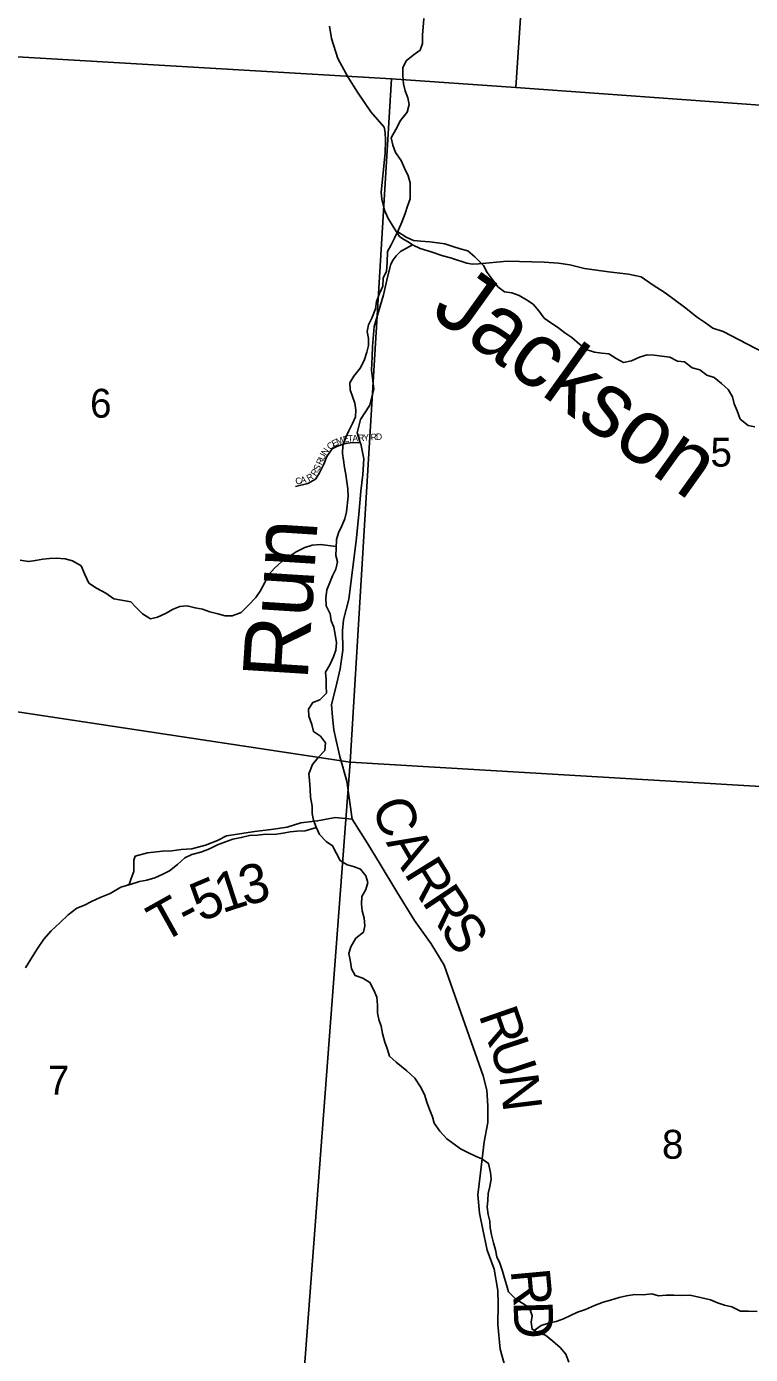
# Model space of a CAD drawing. Extents: x 0 to 34, y 0 to 22.
# Drawn here: x 28.342 to 29.394, y 15.21 to 17.138 of the extents above; entities that cross this region are included whole.
import ezdxf

# ---------------------------------------------------------------- set-up
doc = ezdxf.new("R2010")
doc.units = 0
for name, color, linetype in [('GM_X_County_Road', 7, 'Continuous'), ('GM_X_County_Road_Text', 7, 'Continuous'), ('GM_X_Minor_River', 7, 'Continuous'), ('GM_X_Minor_River_Text', 7, 'Continuous'), ('GM_X_Section', 7, 'Continuous'), ('GM_X_Section_Text', 7, 'Continuous'), ('GM_X_State_Route', 7, 'Continuous'), ('GM_X_Township_Road', 7, 'Continuous'), ('GM_X_Township_Road_Text', 7, 'Continuous'), ('GM_X_Township_Subdivision', 7, 'Continuous'), ('GM_X_Township_Subdivision_Text', 7, 'Continuous')]:
    doc.layers.add(name, color=color, linetype=linetype)

msp = doc.modelspace()

# ---------------------------------------------------------------- linework, layer by layer
at = {"layer": 'GM_X_County_Road'}
msp.add_lwpolyline([(29.036, 15.1969), (29.03, 15.2174), (29.0267, 15.2535), (29.0272, 15.2831), (29.0265, 15.3025), (29.0212, 15.3336), (29.0111, 15.3613), (29.0047, 15.3914), (29.0002, 15.4149), (28.9976, 15.4415), (29.0015, 15.4734), (29.0066, 15.5185), (29.012, 15.5466), (29.0121, 15.5709), (29.0106, 15.5933), (29.0053, 15.6142), (28.9643, 15.7309), (28.9485, 15.775), (28.9296, 15.8058), (28.9054, 15.8396), (28.8798, 15.8815), (28.8556, 15.9214), (28.8367, 15.9526), (28.8148, 15.9869), (28.8074, 16.0419), (28.7972, 16.0777), (28.7916, 16.1012), (28.7882, 16.1168), (28.7864, 16.135), (28.7849, 16.1536), (28.7911, 16.1783), (28.7976, 16.2052), (28.8015, 16.2325), (28.8012, 16.261), (28.8023, 16.2762), (28.8104, 16.3065), (28.8209, 16.3911), (28.8248, 16.4291), (28.8275, 16.4629), (28.8307, 16.4871), (28.8322, 16.5099), (28.8274, 16.5316), (28.8267, 16.5336), (28.8221, 16.5479), (28.8271, 16.5672), (28.8408, 16.5881), (28.8466, 16.6116), (28.8432, 16.6389), (28.844, 16.6583), (28.8445, 16.6731), (28.8472, 16.7023), (28.8606, 16.7482), (28.8669, 16.7756), (28.8713, 16.7926), (28.8745, 16.7988), (28.879, 16.8049), (28.8853, 16.8108), (28.9029, 16.8206)], dxfattribs=at)
at = {"layer": 'GM_X_Minor_River'}
for points in [[(28.919, 17.1492), (28.9183, 17.1367), (28.9173, 17.1257), (28.917, 17.1132), (28.9138, 17.1031), (28.9034, 17.0961), (28.8933, 17.0876), (28.8886, 17.0775), (28.8887, 17.0661), (28.8896, 17.0543), (28.892, 17.0444), (28.8959, 17.0341), (28.898, 17.0245), (28.8947, 17.0132), (28.885, 17.0013), (28.8786, 16.9882), (28.8719, 16.9758), (28.8743, 16.9655), (28.8779, 16.9548), (28.8863, 16.9432), (28.891, 16.9318), (28.8964, 16.921), (28.8992, 16.9107), (28.8994, 16.9001), (28.8991, 16.8876), (28.8954, 16.8767), (28.8922, 16.8661), (28.8873, 16.8537), (28.8825, 16.8424), (28.8766, 16.8304), (28.8715, 16.8207), (28.8663, 16.8109), (28.866, 16.7949)], [(28.8812, 16.8396), (28.8933, 16.8316), (28.9042, 16.8272), (28.9147, 16.8258), (28.928, 16.8251), (28.9389, 16.8237), (28.9495, 16.822), (28.9615, 16.8183), (28.9721, 16.815), (28.983, 16.8121), (28.993, 16.8032), (29.0057, 16.7906)], [(28.866, 16.7949), (28.8648, 16.7824), (28.8603, 16.7721), (28.8596, 16.7607), (28.8547, 16.7501), (28.8506, 16.7383), (28.8491, 16.7277), (28.8434, 16.714), (28.8389, 16.7046), (28.8366, 16.6951), (28.8389, 16.6848), (28.8386, 16.6746), (28.8363, 16.6647), (28.8329, 16.6541), (28.8269, 16.6423), (28.8175, 16.6298), (28.8118, 16.6203), (28.8122, 16.6104), (28.8191, 16.5907), (28.8202, 16.5808), (28.8199, 16.571), (28.8157, 16.5611), (28.8104, 16.5508), (28.8052, 16.5398), (28.8014, 16.5296), (28.801, 16.5178), (28.8022, 16.5079), (28.8041, 16.4973), (28.8057, 16.4875), (28.8072, 16.4765), (28.8087, 16.4666), (28.8091, 16.4552), (28.8069, 16.4332), (28.8043, 16.423), (28.8001, 16.4127), (28.7952, 16.4025), (28.7922, 16.393), (28.7919, 16.3801), (28.7915, 16.3698), (28.7938, 16.3603), (28.7912, 16.3497), (28.7863, 16.3402), (28.7825, 16.3303), (28.7784, 16.3197), (28.7769, 16.3079), (28.7773, 16.2966), (28.783, 16.2848), (28.7845, 16.2749), (28.7883, 16.2655), (28.7903, 16.2549), (28.7922, 16.2431), (28.7911, 16.2321), (28.7877, 16.2226), (28.7828, 16.2108), (28.7764, 16.2002), (28.7771, 16.1899), (28.7775, 16.1805), (28.7776, 16.1698), (28.7681, 16.16), (28.7579, 16.1565), (28.7515, 16.1466), (28.7523, 16.1364), (28.7565, 16.1246), (28.7591, 16.114), (28.769, 16.1072), (28.7762, 16.0977), (28.7751, 16.0864), (28.7656, 16.0765), (28.7573, 16.0662), (28.7521, 16.0529), (28.7532, 16.0434), (28.754, 16.0298), (28.7544, 16.0188), (28.7567, 16.0059), (28.7567, 15.9953), (28.759, 15.9854), (28.7628, 15.9755), (28.7678, 15.9649), (28.7773, 15.9547), (28.7867, 15.9483), (28.7921, 15.9373), (28.7978, 15.9267), (28.8076, 15.9206), (28.8171, 15.9183), (28.8273, 15.9142), (28.8349, 15.9047), (28.838, 15.8952), (28.835, 15.8846), (28.8289, 15.8747), (28.8286, 15.8633), (28.8294, 15.8539), (28.8324, 15.8432), (28.8332, 15.8322), (28.8313, 15.8227), (28.8204, 15.814), (28.8132, 15.8018), (28.8102, 15.792), (28.8125, 15.7798), (28.814, 15.7696), (28.8193, 15.7601), (28.8303, 15.7563)], [(29.0057, 16.7906), (29.011, 16.7807), (29.0186, 16.7709), (29.0266, 16.7599), (29.0364, 16.7523), (29.047, 16.7508), (29.0576, 16.747), (29.0683, 16.741), (29.0781, 16.7345), (29.0861, 16.7247), (29.0937, 16.7144), (29.1035, 16.7073), (29.1134, 16.7012), (29.124, 16.6929), (29.1339, 16.6861), (29.1452, 16.6766), (29.1551, 16.6686), (29.1672, 16.6649), (29.1775, 16.6634), (29.1877, 16.6626), (29.1987, 16.6558), (29.2093, 16.6501), (29.221, 16.6524), (29.2324, 16.6578), (29.2437, 16.6608), (29.2536, 16.6604), (29.2649, 16.6589), (29.2763, 16.6578), (29.2877, 16.6518), (29.2979, 16.651), (29.3089, 16.6419), (29.3199, 16.6393), (29.3301, 16.6314), (29.3407, 16.628), (29.3513, 16.6192), (29.3612, 16.6105), (29.3673, 16.5999), (29.37, 16.5901), (29.3741, 16.5798), (29.3787, 16.5677), (29.3901, 16.5582), (29.3999, 16.5567)], [(28.792, 16.3827), (28.7691, 16.3857), (28.7567, 16.3849), (28.7461, 16.3811), (28.7336, 16.375), (28.7234, 16.3682), (28.7128, 16.361), (28.7022, 16.3515), (28.6939, 16.342), (28.6882, 16.3306), (28.6815, 16.318), (28.675, 16.3085), (28.6645, 16.2975), (28.6539, 16.2869), (28.6406, 16.2819), (28.6304, 16.2819), (28.6198, 16.2849), (28.6084, 16.2879), (28.5975, 16.2917), (28.5869, 16.2936), (28.5755, 16.2966), (28.5649, 16.2955), (28.555, 16.2917), (28.5441, 16.2856), (28.5324, 16.2802), (28.5221, 16.2779), (28.5104, 16.2848), (28.5009, 16.2946), (28.4937, 16.3022)], [(28.4937, 16.3022), (28.4689, 16.3066), (28.4573, 16.3152), (28.4435, 16.3223), (28.4323, 16.3297), (28.4268, 16.3423), (28.4214, 16.3545), (28.409, 16.362), (28.3981, 16.3648), (28.3849, 16.3658), (28.3754, 16.3653), (28.3655, 16.3643), (28.3549, 16.3626), (28.3447, 16.3609), (28.333, 16.363)], [(28.7633, 15.9746), (28.7466, 15.9698), (28.7348, 15.9694), (28.725, 15.9687), (28.7148, 15.9667), (28.7019, 15.9648), (28.6894, 15.9652), (28.6773, 15.9636), (28.6659, 15.9632), (28.6538, 15.9602), (28.6417, 15.9579), (28.6311, 15.9541), (28.6194, 15.9495), (28.608, 15.9438), (28.5952, 15.9389), (28.5823, 15.9354), (28.5721, 15.9308), (28.5615, 15.921), (28.5498, 15.9118), (28.5392, 15.9065), (28.5282, 15.9019), (28.5169, 15.8985), (28.5063, 15.8966), (28.4938, 15.8924)], [(28.4938, 15.8924), (28.4792, 15.8884), (28.4635, 15.8788), (28.449, 15.8734), (28.4364, 15.8672), (28.4261, 15.8621), (28.415, 15.8578), (28.4027, 15.8481), (28.3904, 15.8366), (28.3777, 15.8247), (28.3672, 15.8128), (28.3579, 15.7993), (28.3485, 15.7835), (28.3407, 15.7712)], [(28.8303, 15.7563), (28.8409, 15.7499), (28.8466, 15.7389), (28.8508, 15.7283), (28.8516, 15.7169), (28.8516, 15.7059), (28.8536, 15.696), (28.857, 15.6866), (28.8589, 15.6756), (28.8627, 15.6634), (28.8661, 15.654), (28.8692, 15.643), (28.8791, 15.6342), (28.8942, 15.6214), (28.906, 15.6108), (28.9143, 15.5983), (28.92, 15.5873), (28.9235, 15.5763), (28.9269, 15.5668), (28.9319, 15.555), (28.9341, 15.5455), (28.9425, 15.5342), (28.9524, 15.5228), (28.963, 15.5149), (28.9725, 15.5084), (28.9842, 15.5027), (28.9941, 15.4978), (29.0035, 15.4937), (29.013, 15.4872), (29.0161, 15.474), (29.0169, 15.4645), (29.015, 15.4535), (29.0124, 15.4436), (29.012, 15.4337), (29.0113, 15.4239), (29.0128, 15.4132), (29.0151, 15.4034), (29.0155, 15.3939), (29.0174, 15.3837), (29.0201, 15.3719), (29.0231, 15.3617), (29.0254, 15.3518), (29.0296, 15.3423), (29.0334, 15.3309), (29.0361, 15.3207), (29.0391, 15.3108), (29.0422, 15.3006), (29.0532, 15.2896), (29.0631, 15.2836), (29.0725, 15.2775), (29.0767, 15.2661), (29.0749, 15.2566), (29.0764, 15.2464), (29.0862, 15.2407), (29.0957, 15.2377), (29.1063, 15.229), (29.117, 15.2199), (29.1253, 15.2104), (29.1299, 15.1987)], [(29.0796, 15.2445), (29.0896, 15.2521), (29.1002, 15.2552), (29.1116, 15.2578), (29.1222, 15.2617), (29.132, 15.2666), (29.1422, 15.2712), (29.1539, 15.275), (29.1668, 15.2807), (29.1797, 15.286), (29.1903, 15.2887), (29.2028, 15.2925), (29.2137, 15.2952), (29.2255, 15.2971), (29.2383, 15.2964), (29.2504, 15.2979), (29.2599, 15.2949), (29.2713, 15.296), (29.2823, 15.2957), (29.2936, 15.2953), (29.3054, 15.2957), (29.3167, 15.2935), (29.3357, 15.2893), (29.3459, 15.2848), (29.3557, 15.2814), (29.3663, 15.2791), (29.3789, 15.2727), (29.3906, 15.2727), (29.4035, 15.272)]]:
    msp.add_lwpolyline(points, dxfattribs=at)
at = {"layer": 'GM_X_Section'}
for points in [[(28.157, 18.0791), (28.5064, 18.0521), (28.5033, 18.0906), (29.1178, 18.0184), (29.0528, 17.0493), (28.8721, 17.0617), (28.0732, 17.1088)], [(29.1178, 18.0184), (30.1374, 17.9516), (30.0764, 16.9749), (29.8965, 16.988), (29.0528, 17.0493)], [(28.0732, 17.1088), (28.8721, 17.0617), (28.8121, 16.0697), (28.0465, 16.1852)], [(28.8721, 17.0617), (29.0528, 17.0493), (29.8965, 16.988), (29.8251, 16.0098), (28.8121, 16.0697)], [(28.0441, 16.1595), (28.0465, 16.1852), (28.8121, 16.0697), (28.7351, 15.051), (27.9603, 15.1837)], [(28.8121, 16.0697), (29.8251, 16.0098), (29.7516, 14.9839), (28.7351, 15.051)]]:
    msp.add_lwpolyline(points, close=True, dxfattribs=at)
at = {"layer": 'GM_X_State_Route'}
for points in [[(28.8626, 16.9494), (28.8631, 16.9538), (28.8636, 16.9721), (28.8628, 16.9839), (28.8613, 16.9915), (28.842, 17.0136), (28.8227, 17.0423), (28.8088, 17.0644), (28.7943, 17.0911), (28.7852, 17.1202), (28.782, 17.1379)], [(28.9596, 16.8012), (28.9465, 16.8046), (28.9299, 16.8104), (28.9138, 16.8152), (28.9029, 16.8206), (28.8962, 16.8249), (28.8899, 16.8286), (28.884, 16.8326), (28.8749, 16.8462), (28.8668, 16.86), (28.8619, 16.8712), (28.8579, 16.8872), (28.8571, 16.8972), (28.8626, 16.9494)], [(29.4237, 16.6588), (29.354, 16.6951), (29.3389, 16.6995), (29.3284, 16.7076), (29.3167, 16.7154), (29.2976, 16.7301), (29.2698, 16.751), (29.2506, 16.763), (29.2347, 16.774), (29.2162, 16.7783), (29.1874, 16.7813), (29.1526, 16.7864), (29.131, 16.7916), (29.1147, 16.7941), (29.0938, 16.7957), (29.0404, 16.7969), (28.9992, 16.793), (28.9897, 16.7927), (28.9817, 16.7942), (28.9606, 16.8009), (28.9596, 16.8012)]]:
    msp.add_lwpolyline(points, dxfattribs=at)
at = {"layer": 'GM_X_Township_Road'}
msp.add_lwpolyline([(28.4882, 15.8909), (28.4909, 15.892), (28.4939, 15.9008), (28.4981, 15.911), (28.4978, 15.922), (28.4978, 15.9273), (28.4997, 15.9334), (28.5179, 15.9382), (28.5396, 15.9404), (28.5532, 15.9412), (28.5665, 15.943), (28.5821, 15.9441), (28.6022, 15.9493), (28.6193, 15.9561), (28.6326, 15.9625), (28.6736, 15.9688), (28.6975, 15.9718), (28.7207, 15.9755), (28.7404, 15.9818), (28.7647, 15.9844), (28.7776, 15.987), (28.7901, 15.9892), (28.8148, 15.9869)], dxfattribs=at)
at = {"layer": 'GM_X_Township_Subdivision'}
msp.add_lwpolyline([(28.7328, 16.4697), (28.7508, 16.4743), (28.762, 16.4807), (28.7669, 16.4889), (28.7738, 16.5023), (28.7781, 16.5133), (28.7862, 16.5244), (28.7936, 16.5284), (28.8036, 16.5319), (28.8122, 16.5331), (28.8267, 16.5336)], dxfattribs=at)

# ---------------------------------------------------------------- texts
at = {"layer": 'GM_X_County_Road_Text'}
for s, rotation, p in [('C', 289.789, (28.843, 16.0073)), ('A', 300.148, (28.8635, 15.9532)), ('R', 301.6925, (28.8895, 15.9085)), ('R', 303.7709, (28.9153, 15.8669)), ('S', 302.9468, (28.9411, 15.8283)), ('R', 289.1188, (28.9983, 15.7029)), ('U', 288.1746, (29.0135, 15.6591)), ('N', 277.0704, (29.0285, 15.6144)), ('R', 275.2531, (29.0452, 15.3322)), ('D', 271.6395, (29.0494, 15.2867))]:
    msp.add_text(s, height=0.0568, rotation=rotation, dxfattribs=at).set_placement(p)
at = {"layer": 'GM_X_Minor_River_Text'}
for s, height, rotation, p in [('Jackson', 0.0947, 324.3971, (28.9269, 16.7191)), ('Run', 0.09471, 86.3499, (28.7502, 16.1873))]:
    msp.add_text(s, height=height, rotation=rotation, dxfattribs=at).set_placement(p)
at = {"layer": 'GM_X_Section_Text'}
for s, p in [('6', (28.4343, 16.5698)), ('5', (29.3355, 16.4987)), ('7', (28.373, 15.587)), ('8', (29.2651, 15.494))]:
    msp.add_text(s, height=0.0419, rotation=0, dxfattribs=at).set_placement(p)
at = {"layer": 'GM_X_Township_Road_Text'}
for s, rotation, p in [('3', 14.0514, (28.6586, 15.8608)), ('5', 22.9649, (28.5953, 15.837)), ('1', 18.0351, (28.6263, 15.8502)), ('T', 29.1724, (28.5389, 15.8063)), ('-', 27.3121, (28.5756, 15.8268))]:
    msp.add_text(s, height=0.0568, rotation=rotation, dxfattribs=at).set_placement(p)
at = {"layer": 'GM_X_Township_Subdivision_Text'}
for s, rotation, p in [('M', 22.1126, (28.7939, 16.5299)), ('E', 9.3815, (28.8026, 16.5335)), ('T', 4.514, (28.809, 16.5346)), ('A', 3.6527, (28.8156, 16.5351)), ('R', 3.5006, (28.8239, 16.5356)), ('Y', 3.5236, (28.8314, 16.5361)), ('R', 3.5248, (28.8422, 16.5367)), ('D', 3.5, (28.8497, 16.5372)), ('N', 55.4127, (28.7769, 16.5142)), ('C', 40.1165, (28.7829, 16.5225)), ('E', 26.565, (28.7881, 16.527)), ('S', 63.432, (28.7665, 16.4915)), ('R', 66.4039, (28.7708, 16.5002)), ('U', 65.8201, (28.7738, 16.507)), ('C', 12.4103, (28.7336, 16.4724)), ('A', 12.535, (28.7409, 16.474)), ('R', 30.8194, (28.7521, 16.477)), ('R', 58.0519, (28.762, 16.4842))]:
    msp.add_text(s, height=0.00947, rotation=rotation, dxfattribs=at).set_placement(p)

doc.saveas('drawing.dxf')
